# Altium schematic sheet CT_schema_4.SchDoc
size 287 x 169 mm
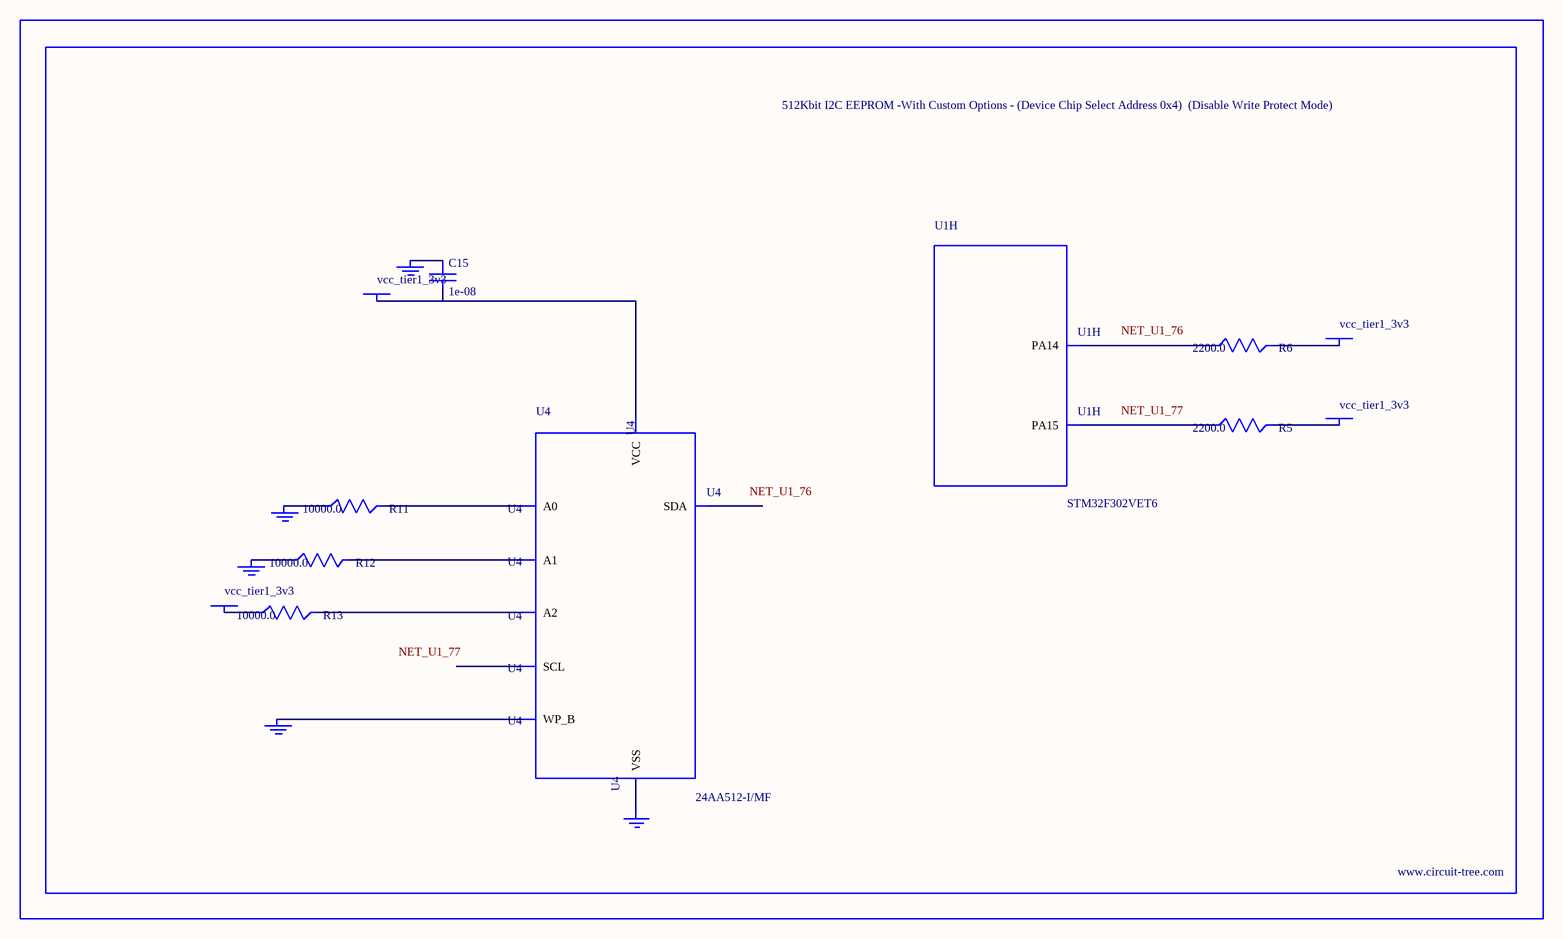
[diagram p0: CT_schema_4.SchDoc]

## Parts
BORDER3  (no value)
C15  1e-08  [C0402]
GND_INSTANCE_3_0  (no value)
GND_INSTANCE_3_1  (no value)
GND_INSTANCE_3_2  (no value)
GND_INSTANCE_3_3  (no value)
GND_INSTANCE_3_4  (no value)
POWER_INSTANCE_3_0  vcc_tier1_3v3
POWER_INSTANCE_3_1  vcc_tier1_3v3
POWER_INSTANCE_3_2  vcc_tier1_3v3
POWER_INSTANCE_3_3  vcc_tier1_3v3
R5  2200.0  [R0603]
R6  2200.0  [R0603]
R11  10000.0  [R0603]
R12  10000.0  [R0603]
R13  10000.0  [R0603]
U1  STM32F302VET6  [LQFP100]  (part H of 8)
U4  24AA512-I/MF  [DFN8-S]

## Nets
NetC15_1: C15.1 GND_INSTANCE_3_3.0(GND)
NetC15_2: C15.2 POWER_INSTANCE_3_1.0(PWR) U4.8(VCC)
NetGND_INSTANCE_3_0_0: GND_INSTANCE_3_0.0(GND) R11.1
NetGND_INSTANCE_3_1_0: GND_INSTANCE_3_1.0(GND) R12.1
NetGND_INSTANCE_3_2_0: GND_INSTANCE_3_2.0(GND) U4.7(WP_B)
NetGND_INSTANCE_3_4_0: GND_INSTANCE_3_4.0(GND) U4.4(VSS)
NetPOWER_INSTANCE_3_0_0: POWER_INSTANCE_3_0.0(PWR) R13.1
NetPOWER_INSTANCE_3_2_0: POWER_INSTANCE_3_2.0(PWR) R6.2
NetPOWER_INSTANCE_3_3_0: POWER_INSTANCE_3_3.0(PWR) R5.2
NetR5_1: R5.1 U1.77(PA15)
NetR6_1: R6.1 U1.76(PA14)
NetR11_2: R11.2 U4.1(A0)
NetR12_2: R12.2 U4.2(A1)
NetR13_2: R13.2 U4.3(A2)

Not connected (* = marked no-connect by the designer): U4 5(SDA) 6(SCL)

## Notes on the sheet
- Labels drawn without touching a wire or pin: NET_U1_76, NET_U1_77

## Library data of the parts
BORDER3 = BORDER_PAGE3
C15 = C0402C103K3RAC
GND_INSTANCE_3_0-GND_INSTANCE_3_4 = GND
POWER_INSTANCE_3_0-POWER_INSTANCE_3_3 = PWR
R5 R6 = RC0603JR-072K2L
R11-R13 = RC0603JR-0710KL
